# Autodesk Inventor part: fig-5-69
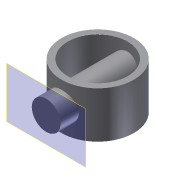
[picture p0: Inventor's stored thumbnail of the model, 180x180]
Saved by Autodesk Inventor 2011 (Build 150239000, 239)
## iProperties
Shininess: 64.0
Length Units: 11269
Angle Units: 11279
Time Units: 11290
Mass Units: 11283
Length Display Precision: 3
Angle Display Precision: 2
Compacted: True
Part Number: fig-5-69
Document SubType Name: Modeling
Created: 2002-12
Designer: deepak
Density: 1 g/cm^3
Density: 0.0
Volumn: 0.0
Area: 0.0
PropertySet Name: Model Information
Control State: 0
Master: False
Checked Out: False
Author: deepak
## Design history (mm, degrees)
sketch "Sketch1"
  geometry: C1 r 23.454 at (0, 0); C2 r 19.43 at (0, 0)
  constraints: 2 centre point, 1 coincident, 1 concentric
extrude "Extrusion1" new body sketch "Sketch1" stored distance "d0" = 30; taper "d1" = 0 deg
workplane "Work Plane1"
workplane "Work Plane2"
sketch "Sketch2"
  geometry: C1 r 9.343 at (0, 0)
  constraints: 1 centre point
extrude "Extrusion2" join sketch "Sketch2" stored distance "d4" = 10; taper "d5" = 0 deg
body "Solid1"
